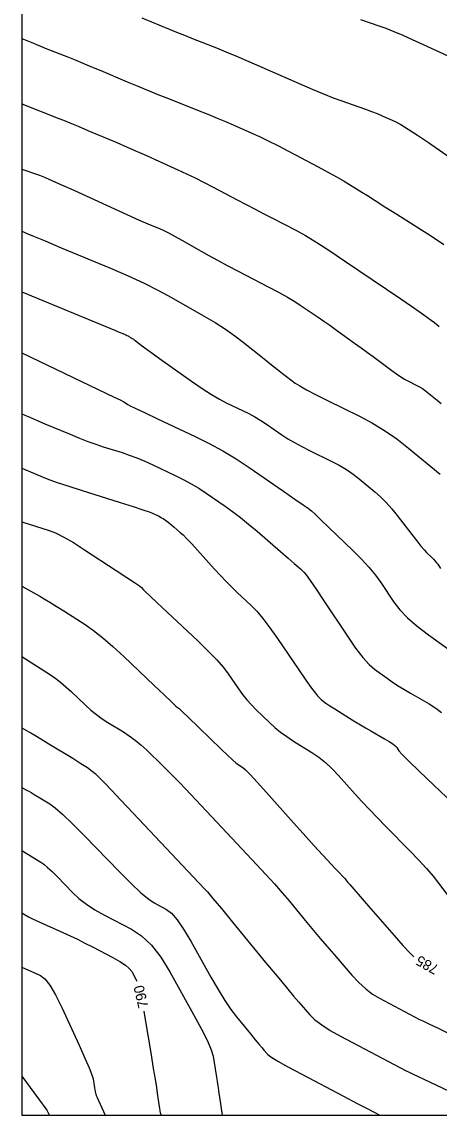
# Model space of a CAD drawing. Extents: x 2082232 to 2083549, y 592624 to 593832.
# Drawn here: x 2082231.8 to 2082260.3, y 592623.8 to 592698.4 of the extents above; entities that cross this region are included whole.
import ezdxf

# ---------------------------------------------------------------- set-up
doc = ezdxf.new("R2010")
doc.units = 0
for name, color, linetype in [('DT_X_Contour_Major', 7, 'Continuous'), ('DT_X_Contour_Minor', 7, 'Continuous'), ('DT_X_TIN_Hull', 7, 'Continuous')]:
    doc.layers.add(name, color=color, linetype=linetype)

msp = doc.modelspace()

# ---------------------------------------------------------------- linework, layer by layer
at = {"layer": 'DT_X_Contour_Major'}
for points in [[(2082239.982, 592698.633), (2082241.296, 592698.095), (2082241.802, 592697.889), (2082242.335, 592697.674), (2082242.894, 592697.45), (2082243.48, 592697.218), (2082245.078, 592696.586), (2082245.722, 592696.326), (2082246.454, 592696.021), (2082247.274, 592695.67), (2082248.183, 592695.275), (2082250.725, 592694.159), (2082251.617, 592693.773), (2082252.388, 592693.452), (2082253.036, 592693.195), (2082253.563, 592693.003), (2082254.806, 592692.575), (2082255.255, 592692.417), (2082255.669, 592692.261), (2082256.049, 592692.108), (2082256.394, 592691.958), (2082257.268, 592691.562), (2082257.657, 592691.361), (2082258.169, 592691.056), (2082258.804, 592690.646), (2082259.561, 592690.132), (2082261.745, 592688.622)], [(2082231.787, 592679.951), (2082238.187, 592677.305), (2082238.315, 592677.252), (2082238.79, 592677.054), (2082238.881, 592677.015), (2082238.962, 592676.977), (2082239.035, 592676.941), (2082239.099, 592676.906), (2082239.259, 592676.815), (2082239.319, 592676.779), (2082239.383, 592676.737), (2082239.448, 592676.689), (2082239.516, 592676.637), (2082239.699, 592676.49), (2082239.854, 592676.374), (2082240.182, 592676.138), (2082240.682, 592675.78), (2082241.355, 592675.301), (2082243.379, 592673.863), (2082244.096, 592673.366), (2082244.728, 592672.955), (2082245.276, 592672.629), (2082245.739, 592672.389), (2082246.862, 592671.862), (2082247.279, 592671.655), (2082247.69, 592671.43), (2082248.093, 592671.187), (2082248.489, 592670.926), (2082249.535, 592670.206), (2082249.948, 592669.935), (2082250.402, 592669.665), (2082250.896, 592669.394), (2082251.431, 592669.123), (2082252.913, 592668.399), (2082253.449, 592668.121), (2082253.946, 592667.827), (2082254.403, 592667.519), (2082254.821, 592667.196), (2082255.884, 592666.314), (2082256.279, 592665.964), (2082256.667, 592665.577), (2082257.047, 592665.152), (2082257.42, 592664.688), (2082258.406, 592663.402), (2082258.746, 592662.964), (2082259.027, 592662.615), (2082259.25, 592662.354), (2082259.414, 592662.181), (2082259.772, 592661.838), (2082259.899, 592661.713), (2082260.009, 592661.593), (2082260.104, 592661.479), (2082260.182, 592661.37), (2082260.37, 592661.089)], [(2082231.787, 592659.888), (2082233.018, 592659.188), (2082233.317, 592659.013), (2082233.688, 592658.788), (2082234.13, 592658.513), (2082234.643, 592658.188), (2082236.105, 592657.255), (2082236.682, 592656.856), (2082237.316, 592656.36), (2082238.006, 592655.767), (2082238.754, 592655.076), (2082240.822, 592653.104), (2082241.503, 592652.455), (2082241.997, 592651.987), (2082242.303, 592651.701), (2082242.422, 592651.595), (2082242.487, 592651.555), (2082242.521, 592651.53), (2082242.574, 592651.484), (2082242.646, 592651.419), (2082242.736, 592651.332), (2082243.148, 592650.933), (2082245.399, 592648.758), (2082245.825, 592648.35), (2082246.161, 592648.04), (2082246.408, 592647.825), (2082246.566, 592647.706), (2082246.867, 592647.519), (2082247.052, 592647.359), (2082247.384, 592647.022), (2082247.863, 592646.507), (2082248.487, 592645.814), (2082250.346, 592643.729), (2082250.995, 592643.004), (2082251.547, 592642.392), (2082252.003, 592641.893), (2082252.361, 592641.507), (2082253.189, 592640.629), (2082253.467, 592640.333), (2082253.68, 592640.104), (2082253.83, 592639.941), (2082253.914, 592639.844), (2082254.054, 592639.674), (2082254.182, 592639.524), (2082254.459, 592639.203), (2082254.887, 592638.709), (2082255.464, 592638.044), (2082257.204, 592636.04), (2082257.796, 592635.371), (2082258.268, 592634.868), (2082258.56, 592634.587)], [(2082231.787, 592637.596), (2082232.121, 592637.383), (2082232.245, 592637.316), (2082232.476, 592637.204), (2082232.812, 592637.049), (2082233.255, 592636.85), (2082234.576, 592636.259), (2082235.075, 592636.032), (2082235.581, 592635.791), (2082236.094, 592635.537), (2082236.614, 592635.27), (2082238.01, 592634.542), (2082238.482, 592634.277), (2082238.853, 592634.029), (2082239.121, 592633.798), (2082239.287, 592633.584), (2082239.593, 592633.035), (2082239.635, 592632.929)], [(2082240.108, 592630.886), (2082240.159, 592630.602), (2082240.607, 592627.906), (2082240.759, 592626.985), (2082240.88, 592626.245), (2082240.97, 592625.684), (2082241.029, 592625.304), (2082241.143, 592624.529), (2082241.182, 592624.272), (2082241.213, 592624.082), (2082241.235, 592623.959), (2082241.249, 592623.903), (2082241.296, 592623.798)]]:
    msp.add_lwpolyline(points, dxfattribs=at)
at = {"layer": 'DT_X_Contour_Minor'}
for points in [[(2082254.918, 592698.532), (2082256.157, 592698.106), (2082256.648, 592697.928), (2082257.192, 592697.713), (2082257.789, 592697.462), (2082258.439, 592697.173), (2082260.244, 592696.356), (2082260.924, 592696.035)], [(2082231.787, 592697.236), (2082232.579, 592696.906), (2082232.782, 592696.823), (2082233.052, 592696.714), (2082233.39, 592696.578), (2082233.795, 592696.418), (2082234.964, 592695.954), (2082235.431, 592695.767), (2082235.957, 592695.552), (2082236.542, 592695.309), (2082237.185, 592695.04), (2082238.978, 592694.283), (2082239.658, 592693.998), (2082240.356, 592693.711), (2082241.07, 592693.422), (2082241.801, 592693.13), (2082243.774, 592692.35), (2082244.482, 592692.068), (2082245.124, 592691.805), (2082245.703, 592691.564), (2082246.217, 592691.342), (2082247.501, 592690.779), (2082248.017, 592690.543), (2082248.604, 592690.26), (2082249.261, 592689.929), (2082249.989, 592689.55), (2082252.023, 592688.476), (2082252.729, 592688.099), (2082253.322, 592687.774), (2082253.802, 592687.5), (2082254.169, 592687.279), (2082254.998, 592686.758), (2082255.381, 592686.517), (2082255.909, 592686.183), (2082256.58, 592685.759), (2082257.396, 592685.242), (2082259.765, 592683.742), (2082260.608, 592683.188)], [(2082231.787, 592692.783), (2082234.323, 592691.777), (2082234.635, 592691.651), (2082235.069, 592691.473), (2082235.623, 592691.241), (2082236.299, 592690.957), (2082238.263, 592690.128), (2082238.98, 592689.823), (2082239.658, 592689.53), (2082240.297, 592689.249), (2082240.897, 592688.98), (2082242.445, 592688.277), (2082243.03, 592688.006), (2082243.625, 592687.72), (2082244.229, 592687.418), (2082244.842, 592687.101), (2082246.49, 592686.236), (2082247.105, 592685.913), (2082247.713, 592685.595), (2082248.315, 592685.28), (2082248.912, 592684.97), (2082250.493, 592684.148), (2082251.146, 592683.787), (2082251.92, 592683.321), (2082252.814, 592682.75), (2082253.828, 592682.073), (2082256.694, 592680.128), (2082257.658, 592679.473), (2082258.402, 592678.966), (2082258.925, 592678.606), (2082259.227, 592678.395), (2082259.739, 592678.029), (2082259.972, 592677.851), (2082260.286, 592677.592)], [(2082231.787, 592688.329), (2082232.985, 592687.903), (2082233.324, 592687.771), (2082233.83, 592687.557), (2082234.501, 592687.26), (2082235.339, 592686.881), (2082239.803, 592684.844), (2082239.87, 592684.815), (2082239.997, 592684.761), (2082240.184, 592684.682), (2082240.433, 592684.578), (2082241.176, 592684.267), (2082241.481, 592684.131), (2082241.84, 592683.953), (2082242.252, 592683.733), (2082242.717, 592683.473), (2082244.029, 592682.725), (2082244.556, 592682.429), (2082245.152, 592682.104), (2082245.817, 592681.749), (2082246.552, 592681.364), (2082248.604, 592680.297), (2082249.318, 592679.919), (2082249.922, 592679.586), (2082250.415, 592679.297), (2082250.797, 592679.053), (2082251.67, 592678.461), (2082252.015, 592678.225), (2082252.395, 592677.96), (2082252.81, 592677.668), (2082253.261, 592677.347), (2082254.51, 592676.455), (2082254.962, 592676.13), (2082255.383, 592675.825), (2082255.772, 592675.54), (2082256.129, 592675.274), (2082257.039, 592674.591), (2082257.365, 592674.353), (2082257.658, 592674.154), (2082257.919, 592673.993), (2082258.147, 592673.871), (2082258.714, 592673.594), (2082258.927, 592673.481), (2082259.141, 592673.349), (2082259.355, 592673.198), (2082259.57, 592673.029), (2082260.144, 592672.553), (2082260.409, 592672.334)], [(2082231.787, 592684.091), (2082231.904, 592684.037), (2082232.083, 592683.962), (2082232.572, 592683.757), (2082233.369, 592683.424), (2082234.475, 592682.962), (2082237.836, 592681.558), (2082239.041, 592681.038), (2082240.138, 592680.533), (2082241.124, 592680.043), (2082242.001, 592679.566), (2082244.194, 592678.315), (2082244.98, 592677.851), (2082245.695, 592677.397), (2082246.337, 592676.954), (2082246.907, 592676.52), (2082248.333, 592675.379), (2082248.829, 592674.983), (2082249.248, 592674.651), (2082249.589, 592674.385), (2082249.854, 592674.183), (2082250.457, 592673.73), (2082250.761, 592673.53), (2082251.222, 592673.268), (2082251.838, 592672.945), (2082252.611, 592672.56), (2082254.88, 592671.452), (2082255.725, 592671.005), (2082256.559, 592670.495), (2082257.381, 592669.922), (2082258.192, 592669.286), (2082260.338, 592667.505)], [(2082231.787, 592675.788), (2082237.574, 592673.022), (2082238.101, 592672.769), (2082238.493, 592672.577), (2082238.75, 592672.446), (2082238.871, 592672.378), (2082239.013, 592672.277), (2082239.18, 592672.187), (2082239.574, 592671.994), (2082240.197, 592671.697), (2082241.047, 592671.296), (2082243.619, 592670.088), (2082244.573, 592669.616), (2082245.506, 592669.105), (2082246.419, 592668.556), (2082247.311, 592667.968), (2082249.661, 592666.35), (2082250.434, 592665.818), (2082250.989, 592665.435), (2082251.327, 592665.201), (2082251.447, 592665.117), (2082251.477, 592665.09), (2082251.565, 592665.008), (2082251.804, 592664.78), (2082252.195, 592664.406), (2082252.739, 592663.887), (2082254.39, 592662.308), (2082254.974, 592661.728), (2082255.486, 592661.169), (2082255.928, 592660.634), (2082256.298, 592660.12), (2082257.191, 592658.782), (2082257.589, 592658.267), (2082258.115, 592657.726), (2082258.769, 592657.159), (2082259.55, 592656.567), (2082261.803, 592654.952)], [(2082231.787, 592671.632), (2082231.982, 592671.543), (2082232.1, 592671.492), (2082232.369, 592671.378), (2082232.79, 592671.201), (2082233.362, 592670.96), (2082235.089, 592670.235), (2082235.717, 592669.978), (2082236.302, 592669.751), (2082236.846, 592669.554), (2082237.348, 592669.387), (2082238.632, 592668.984), (2082239.125, 592668.818), (2082239.64, 592668.623), (2082240.176, 592668.399), (2082240.734, 592668.146), (2082242.253, 592667.433), (2082242.812, 592667.157), (2082243.351, 592666.863), (2082243.87, 592666.553), (2082244.369, 592666.225), (2082245.672, 592665.328), (2082246.175, 592664.969), (2082246.705, 592664.565), (2082247.262, 592664.117), (2082247.847, 592663.623), (2082249.444, 592662.248), (2082249.979, 592661.787), (2082250.385, 592661.433), (2082250.664, 592661.189), (2082250.814, 592661.052), (2082251.044, 592660.832), (2082251.194, 592660.648), (2082251.473, 592660.259), (2082251.879, 592659.667), (2082252.414, 592658.87), (2082254.012, 592656.474), (2082254.576, 592655.659), (2082255.072, 592655.011), (2082255.499, 592654.529), (2082255.857, 592654.213), (2082256.72, 592653.595), (2082257.063, 592653.357), (2082257.445, 592653.109), (2082257.866, 592652.85), (2082258.327, 592652.579), (2082259.606, 592651.844), (2082260.055, 592651.558), (2082260.442, 592651.251)], [(2082231.787, 592667.919), (2082233.234, 592667.311), (2082233.63, 592667.158), (2082234.197, 592666.959), (2082234.936, 592666.715), (2082235.845, 592666.424), (2082238.499, 592665.59), (2082239.384, 592665.309), (2082240.048, 592665.094), (2082240.491, 592664.944), (2082240.714, 592664.859), (2082241.012, 592664.719), (2082241.122, 592664.664), (2082241.227, 592664.607), (2082241.329, 592664.546), (2082241.427, 592664.481), (2082241.683, 592664.305), (2082241.787, 592664.231), (2082241.905, 592664.139), (2082242.039, 592664.03), (2082242.188, 592663.903), (2082242.606, 592663.544), (2082242.796, 592663.367), (2082243.055, 592663.105), (2082243.383, 592662.759), (2082243.778, 592662.329), (2082244.924, 592661.068), (2082245.344, 592660.612), (2082245.746, 592660.191), (2082246.13, 592659.805), (2082246.495, 592659.453), (2082247.443, 592658.561), (2082247.822, 592658.169), (2082248.249, 592657.661), (2082248.723, 592657.037), (2082249.245, 592656.297), (2082250.699, 592654.169), (2082251.188, 592653.46), (2082251.564, 592652.927), (2082251.826, 592652.571), (2082251.976, 592652.393), (2082252.226, 592652.151), (2082252.355, 592652.043), (2082252.553, 592651.899), (2082252.823, 592651.719), (2082253.162, 592651.503), (2082254.161, 592650.879), (2082254.533, 592650.65), (2082254.899, 592650.427), (2082255.26, 592650.213), (2082255.615, 592650.006), (2082256.555, 592649.466), (2082256.871, 592649.277), (2082257.113, 592649.116), (2082257.283, 592648.983), (2082257.379, 592648.878), (2082257.537, 592648.635), (2082257.73, 592648.421), (2082258.193, 592647.962), (2082258.923, 592647.256), (2082259.923, 592646.304), (2082262.946, 592643.439)], [(2082231.787, 592664.265), (2082233.644, 592663.681), (2082234.094, 592663.505), (2082234.647, 592663.227), (2082235.305, 592662.847), (2082236.066, 592662.365), (2082238.236, 592660.945), (2082238.953, 592660.473), (2082239.478, 592660.122), (2082239.81, 592659.892), (2082239.95, 592659.783), (2082240.066, 592659.655), (2082240.202, 592659.521), (2082240.522, 592659.216), (2082241.025, 592658.74), (2082241.713, 592658.093), (2082243.793, 592656.137), (2082244.508, 592655.448), (2082245.094, 592654.845), (2082245.552, 592654.329), (2082245.879, 592653.9), (2082246.582, 592652.873), (2082246.855, 592652.494), (2082247.147, 592652.13), (2082247.458, 592651.78), (2082247.789, 592651.444), (2082248.696, 592650.567), (2082249.053, 592650.242), (2082249.444, 592649.925), (2082249.869, 592649.616), (2082250.327, 592649.316), (2082251.594, 592648.525), (2082252.063, 592648.205), (2082252.52, 592647.84), (2082252.965, 592647.429), (2082253.399, 592646.973), (2082254.539, 592645.695), (2082254.991, 592645.197), (2082255.492, 592644.661), (2082256.042, 592644.089), (2082256.641, 592643.478), (2082258.304, 592641.802), (2082258.893, 592641.194), (2082259.413, 592640.628), (2082259.863, 592640.104), (2082260.243, 592639.621), (2082261.165, 592638.391)], [(2082231.787, 592655.073), (2082233.668, 592653.872), (2082234.05, 592653.615), (2082234.426, 592653.331), (2082234.798, 592653.022), (2082235.165, 592652.688), (2082236.136, 592651.761), (2082236.505, 592651.427), (2082236.882, 592651.119), (2082237.267, 592650.838), (2082237.66, 592650.583), (2082238.72, 592649.939), (2082239.118, 592649.68), (2082239.516, 592649.384), (2082239.915, 592649.051), (2082240.315, 592648.682), (2082241.382, 592647.65), (2082241.78, 592647.26), (2082242.174, 592646.865), (2082242.564, 592646.466), (2082242.95, 592646.061), (2082245.434, 592643.426), (2082247.818, 592640.899), (2082248.451, 592640.218), (2082249.032, 592639.576), (2082249.562, 592638.971), (2082250.039, 592638.405), (2082251.243, 592636.945), (2082251.697, 592636.399), (2082252.154, 592635.855), (2082252.616, 592635.313), (2082253.081, 592634.773), (2082254.327, 592633.338), (2082254.795, 592632.836), (2082255.263, 592632.407), (2082255.732, 592632.051), (2082256.202, 592631.767), (2082258.938, 592630.331), (2082259.156, 592630.223), (2082259.577, 592630.02), (2082260.203, 592629.722), (2082261.033, 592629.329)], [(2082231.787, 592650.22), (2082232.275, 592649.945), (2082232.402, 592649.87), (2082232.669, 592649.71), (2082233.075, 592649.464), (2082233.621, 592649.133), (2082235.262, 592648.136), (2082235.819, 592647.79), (2082236.262, 592647.5), (2082236.589, 592647.267), (2082236.8, 592647.09), (2082237.21, 592646.693), (2082237.462, 592646.438), (2082237.911, 592645.971), (2082238.557, 592645.292), (2082239.399, 592644.4), (2082244.261, 592639.243), (2082244.456, 592639.02), (2082244.838, 592638.567), (2082245.408, 592637.882), (2082246.164, 592636.966), (2082248.432, 592634.216), (2082249.211, 592633.273), (2082249.849, 592632.507), (2082250.344, 592631.917), (2082250.698, 592631.503), (2082251.451, 592630.636), (2082251.794, 592630.301), (2082252.259, 592629.946), (2082252.845, 592629.572), (2082253.553, 592629.178), (2082258.025, 592626.829), (2082258.243, 592626.718), (2082258.516, 592626.583), (2082258.844, 592626.424), (2082259.228, 592626.241), (2082261.398, 592625.217)], [(2082231.787, 592646.156), (2082232.152, 592645.951), (2082232.258, 592645.89), (2082232.418, 592645.795), (2082232.632, 592645.666), (2082232.901, 592645.503), (2082233.691, 592645.022), (2082234.062, 592644.751), (2082234.58, 592644.297), (2082235.246, 592643.661), (2082236.061, 592642.842), (2082238.429, 592640.415), (2082239.246, 592639.598), (2082239.918, 592638.968), (2082240.447, 592638.525), (2082240.832, 592638.268), (2082241.666, 592637.833), (2082242.004, 592637.575), (2082242.392, 592637.128), (2082242.83, 592636.492), (2082243.318, 592635.667), (2082244.686, 592633.216), (2082245.18, 592632.356), (2082245.636, 592631.618), (2082246.054, 592630.999), (2082246.434, 592630.501), (2082247.397, 592629.333), (2082247.725, 592628.936), (2082247.988, 592628.62), (2082248.184, 592628.386), (2082248.314, 592628.233), (2082248.574, 592627.934), (2082248.793, 592627.765), (2082249.254, 592627.485), (2082249.957, 592627.093), (2082250.903, 592626.589), (2082253.749, 592625.094), (2082254.689, 592624.601), (2082255.375, 592624.24), (2082255.806, 592624.014), (2082256.218, 592623.798)], [(2082231.787, 592641.843), (2082233.09, 592641.051), (2082233.287, 592640.912), (2082233.539, 592640.697), (2082233.847, 592640.408), (2082234.211, 592640.043), (2082235.256, 592638.973), (2082235.686, 592638.576), (2082236.191, 592638.189), (2082236.773, 592637.812), (2082237.43, 592637.444), (2082239.284, 592636.477), (2082239.968, 592636.023), (2082240.631, 592635.387), (2082241.273, 592634.569), (2082241.892, 592633.568), (2082243.516, 592630.658), (2082244.056, 592629.662), (2082244.456, 592628.859), (2082244.719, 592628.246), (2082244.842, 592627.826), (2082244.986, 592626.959), (2082245.035, 592626.661), (2082245.075, 592626.416), (2082245.106, 592626.224), (2082245.127, 592626.086), (2082245.171, 592625.787), (2082245.191, 592625.656), (2082245.216, 592625.487), (2082245.246, 592625.28), (2082245.283, 592625.034), (2082245.466, 592623.798)], [(2082231.787, 592633.899), (2082233.069, 592633.327), (2082233.365, 592633.098), (2082233.704, 592632.659), (2082234.086, 592632.007), (2082234.512, 592631.144), (2082235.704, 592628.561), (2082236.099, 592627.692), (2082236.389, 592627.021), (2082236.575, 592626.549), (2082236.656, 592626.275), (2082236.733, 592625.809), (2082236.759, 592625.651), (2082236.779, 592625.529), (2082236.794, 592625.442), (2082236.802, 592625.39), (2082236.815, 592625.298), (2082236.832, 592625.241), (2082236.871, 592625.139), (2082236.933, 592624.992), (2082237.017, 592624.8), (2082237.465, 592623.798)], [(2082231.787, 592626.457), (2082233.485, 592624.133), (2082233.517, 592624.088), (2082233.545, 592624.045), (2082233.568, 592624.004), (2082233.586, 592623.967), (2082233.661, 592623.798)]]:
    msp.add_lwpolyline(points, dxfattribs=at)
at = {"layer": 'DT_X_TIN_Hull'}
msp.add_lwpolyline([(2082231.787, 592700.344), (2082231.787, 592696.655), (2082231.787, 592690.932), (2082231.787, 592688.723), (2082231.787, 592684.555), (2082231.787, 592683.998), (2082231.787, 592683.653), (2082231.787, 592676.01), (2082231.787, 592674.484), (2082231.787, 592671.477), (2082231.787, 592664.893), (2082231.787, 592663.167), (2082231.787, 592662.34), (2082231.787, 592658.71), (2082231.787, 592651.104), (2082231.787, 592650.552), (2082231.787, 592650.436), (2082231.787, 592645.81), (2082231.787, 592638.612), (2082231.787, 592637.739), (2082231.787, 592636.763), (2082231.787, 592632.898), (2082231.787, 592629.229), (2082231.787, 592623.798), (2082233.08, 592623.798), (2082236.296, 592623.798), (2082241.746, 592623.798), (2082247.156, 592623.798), (2082255.817, 592623.798), (2082257.8, 592623.798), (2082258.811, 592623.798), (2082263.441, 592623.798)], dxfattribs=at)

# ---------------------------------------------------------------- texts
at = {"layer": 'DT_X_Contour_Major'}
for s, rotation, p in [('785', 151.03659, (2082260.313, 592633.965)), ('790', 103.04187, (2082240.44, 592631.191))]:
    msp.add_text(s, height=0.7, rotation=rotation, dxfattribs=at).set_placement(p)

doc.saveas('drawing.dxf')
